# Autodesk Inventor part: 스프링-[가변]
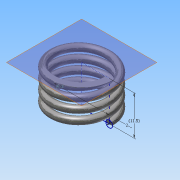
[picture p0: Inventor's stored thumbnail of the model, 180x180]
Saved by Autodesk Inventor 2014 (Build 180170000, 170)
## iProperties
Created: 2015-04
Part Number: 스프링-[가변]
Material: 강철, 탄소
Document SubType Name: Modeling
Designer: Administrator
Density: 7.87 g/cm^3
Appearance: 반연마
Mass: 4.78743 g
Surface Area: 12.5262 cm^2
Volume: 0.608313 cm^3
Author: Administrator
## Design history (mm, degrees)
sketch "스케치1"
  geometry: L1 (0, 0)-(8, 0); L2 (8, 0)-(8, 11.5); L3 (8, 11.5)-(0, 11.5); L4 (0, 11.5)-(0, 0); C1 r 1 at (8, 0)
  constraints: 8 end point, 2 parallel, 1 centre point, 1 coincident, 1 horizontal, 1 perpendicular
  dimensions: "d0" = 16 diameter of L2 L4; "d1" = 11.50049 distance between parallel lines of L1 L3 (derived); "d2" = 2 diameter of C1
feature "코일1" pitch "d3" = 10; turns "d5" = 4; dims "d4" = 11.50049 (= d1), "d6" = 0, angle "d7" = 90 deg, angle "d8" = 90 deg, "d9" = 0, "d10" = 0
sketch "스케치2"
  geometry: L1 (-9, 0)-(-7, 0) reference; 1 further point
  constraints: 1 horizontal alignment
extrude "돌출1" cut sketch "스케치2" stored distance "d11" = 10; taper "d12" = 0 deg
node "작업 평면1"
sketch "스케치3"
  geometry: L1 (9, 0)-(7, 0) reference; 1 further point
  constraints: 1 horizontal alignment
extrude "돌출2" cut sketch "스케치3" stored distance "d13" = 10; taper "d14" = 0 deg
node "솔리드1"
node "절단 모서리 투영1"
node "절단 모서리 투영2"
